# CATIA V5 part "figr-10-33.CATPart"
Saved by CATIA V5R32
Part number: Part1
Bounding box of the stored display mesh (mm): x -193.573 to 205.258, y -140.014 to 12.054, z -96.593 to 19.319
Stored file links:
  D:\PROJECTS\Project 2022\CATIA V5 6R 2022\Resources\Part Files\c10_catia_v5_6r2022_prt\c10_catia_v5_6r2022_prt\figr-10-33.CATPart
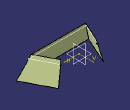
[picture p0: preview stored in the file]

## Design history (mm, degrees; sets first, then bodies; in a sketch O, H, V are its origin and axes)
Body1 (main body)
  Sketch1 on xy-plane, origin (0, 0, 0), H (1, 0, 0), V (0, 1, 0)
    line L1 (-101.4744, 0) -> (-153.3719, -114.1323)
    point P1 (-101.4744, 0)
    line L2 (-153.3719, -114.1323) -> (162.3879, -114.1323)
    line L3 (162.3879, -114.1323) -> (102.3183, 0)
    point P4 (102.3183, 0)
    coincidence: P1 H, P4 H
    horizontal: L2 H
  Sweep1: type Segment, GuideCrv Sketch1, Length1 20, Length2 100, Angle 15, DraftDirection xy-plane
